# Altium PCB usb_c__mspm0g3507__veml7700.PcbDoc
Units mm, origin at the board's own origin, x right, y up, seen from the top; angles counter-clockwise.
Board outline 68 x 40 mm, 2 copper layers (Top, Bottom), stack 0 mm thick; 33 components, 29 nets, 178 pads, 51 vias.
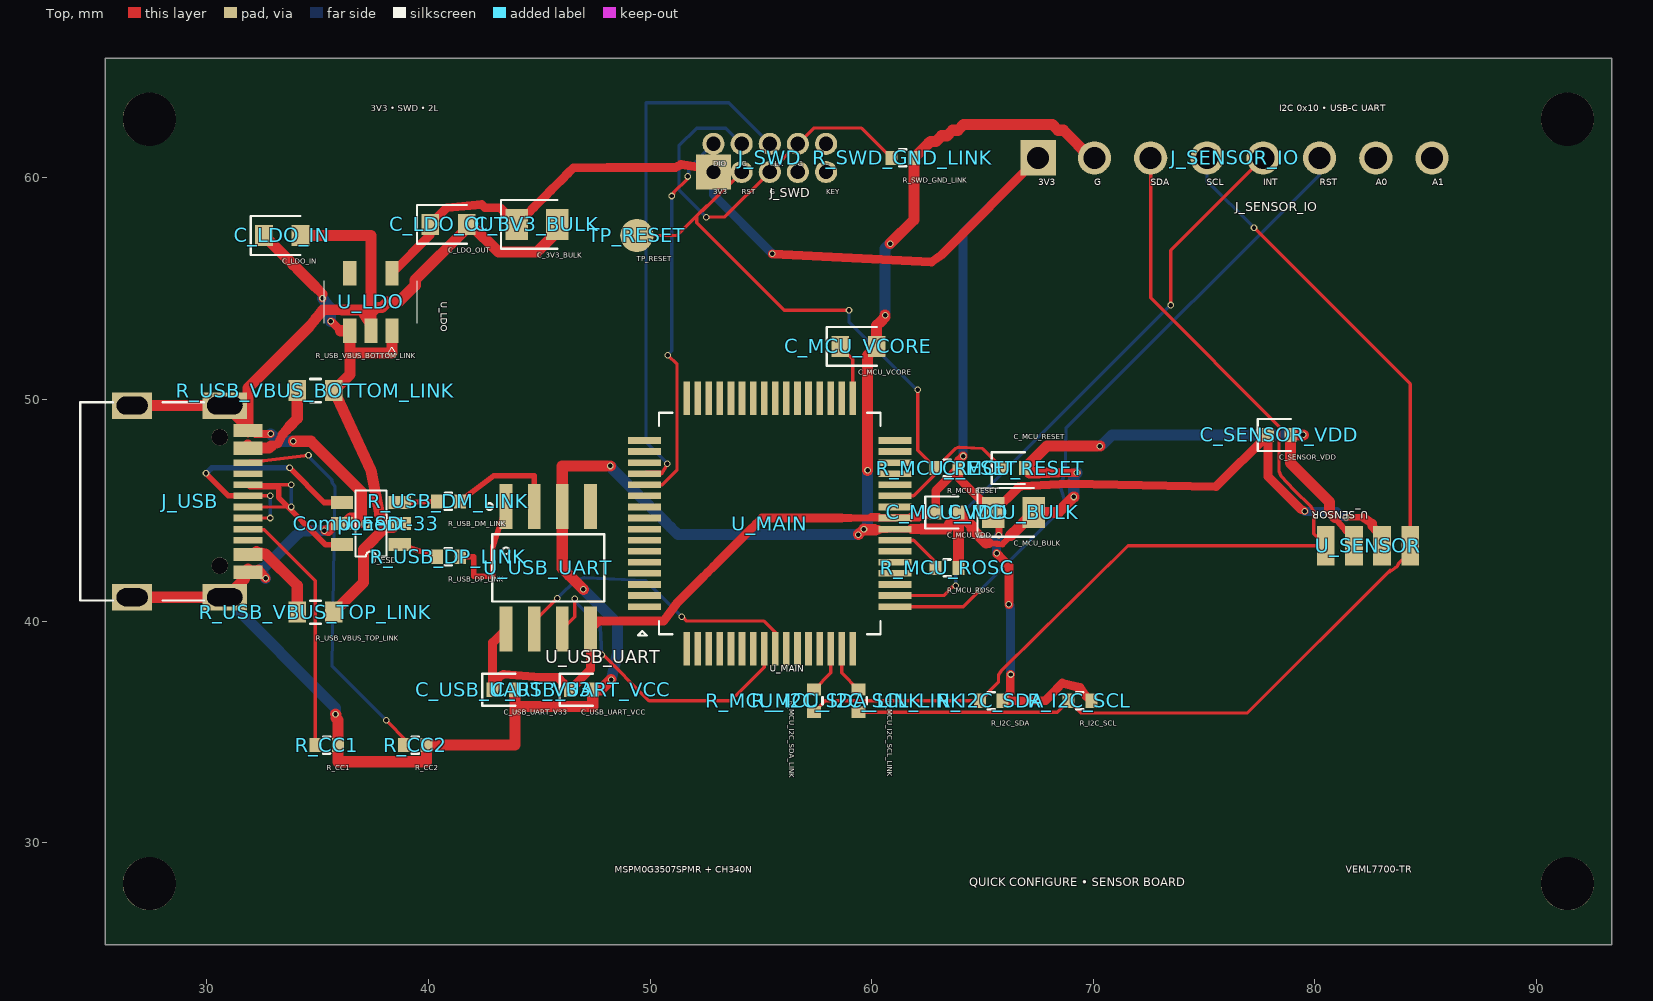
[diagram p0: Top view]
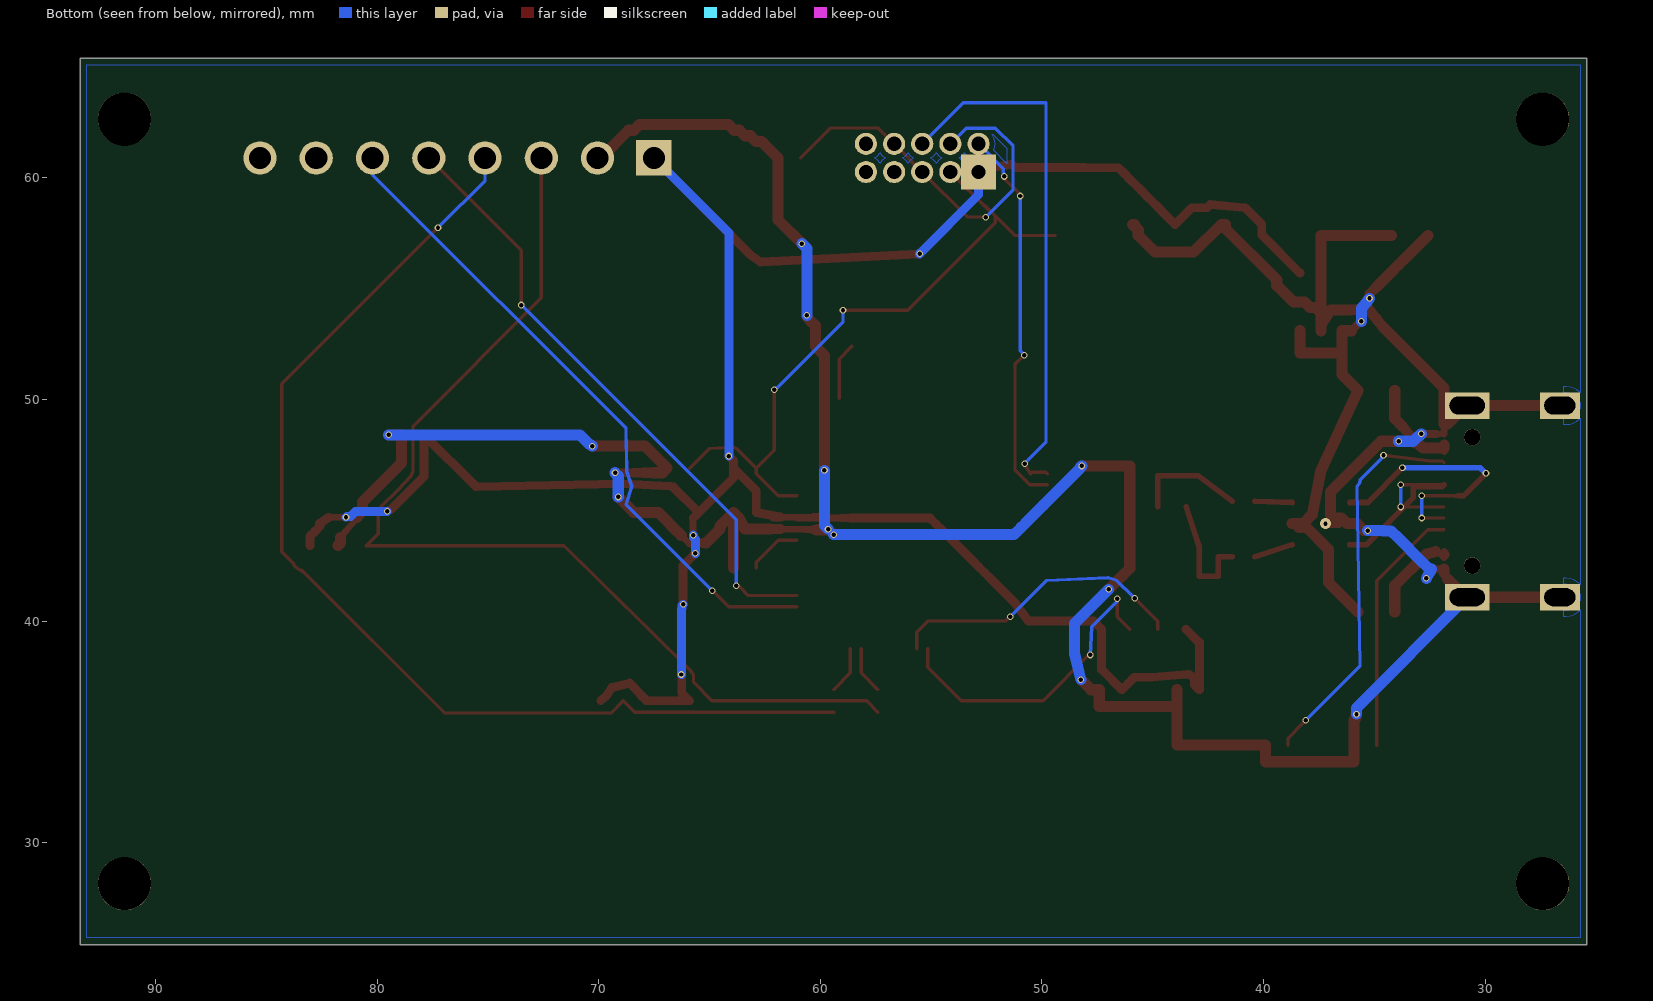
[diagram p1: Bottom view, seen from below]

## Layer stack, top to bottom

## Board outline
25.4,65.4 93.4,65.4 93.4,25.4 25.4,25.4

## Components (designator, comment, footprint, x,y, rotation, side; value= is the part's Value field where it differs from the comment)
C_3V3_BULK "" TSCIRCUIT-2.8500x1.4000mm 44.9,57.9 r0 top
C_LDO_IN "" TSCIRCUIT-2.4500x0.9500mm 33.4,57.4 r0 top
C_LDO_OUT "" TSCIRCUIT-2.4500x0.9500mm 40.9,57.9 r0 top
C_MCU_BULK "" TSCIRCUIT-2.8500x1.4000mm 66.4,44.9 r0 top
C_MCU_RESET "" TSCIRCUIT-1.5600x0.6400mm 66.4,46.9 r0 top
C_MCU_VCORE "" TSCIRCUIT-2.4500x0.9500mm 59.4,52.4 r0 top
C_MCU_VDD "" TSCIRCUIT-1.5600x0.6400mm 63.4,44.9 r0 top
C_SENSOR_VDD "" TSCIRCUIT-1.5600x0.6400mm 78.4,48.4 r0 top
C_USB_UART_V33 "" TSCIRCUIT-1.5600x0.6400mm 43.4,36.9 r0 top
C_USB_UART_VCC "" TSCIRCUIT-1.5600x0.6400mm 46.9,36.9 r0 top
Component-33 "" TSCIRCUIT-0.5000x0.5000mm 37.2,44.4 r0 top
J_SENSOR_IO "" TSCIRCUIT-19.2800x1.5000mm 76.4,60.9 r0 top
J_SWD "" TSCIRCUIT-6.0800x2.2700mm 55.4,60.9 r0 top
J_USB "" TSCIRCUIT-6.7732x9.8502mm 29.112,45.4 r90 top
R_CC1 "" TSCIRCUIT-1.5600x0.6400mm 35.4,34.4 r0 top
R_CC2 "" TSCIRCUIT-1.5600x0.6400mm 39.4,34.4 r0 top
R_I2C_SCL "" TSCIRCUIT-1.5600x0.6400mm 69.4,36.4 r0 top
R_I2C_SDA "" TSCIRCUIT-1.5600x0.6400mm 65.4,36.4 r0 top
R_MCU_I2C_SCL_LINK "" TSCIRCUIT-0.6400x1.5600mm 59.4,36.4 r270 top
R_MCU_I2C_SDA_LINK "" TSCIRCUIT-0.6400x1.5600mm 57.4,36.4 r270 top
R_MCU_RESET "" TSCIRCUIT-1.5600x0.6400mm 63.4,46.9 r0 top
R_MCU_ROSC "" TSCIRCUIT-1.5600x0.6400mm 63.4,42.4 r0 top
R_SWD_GND_LINK "" TSCIRCUIT-1.5600x0.6400mm 61.4,60.9 r0 top
R_USB_DM_LINK "" TSCIRCUIT-1.5600x0.6400mm 40.9,45.4 r0 top
R_USB_DP_LINK "" TSCIRCUIT-1.5600x0.6400mm 40.9,42.9 r0 top
R_USB_VBUS_BOTTOM_LINK "" TSCIRCUIT-2.4500x0.9500mm 34.9,50.4 r0 top
R_USB_VBUS_TOP_LINK "" TSCIRCUIT-2.4500x0.9500mm 34.9,40.4 r0 top
TP_RESET "" TSCIRCUIT-1.5000x1.5000mm 49.4,57.4 r0 top
U_ESD "" TSCIRCUIT-3.6000x2.5000mm 37.4,44.4 r0 top
U_LDO "" TSCIRCUIT-2.5000x3.7000mm 37.4,54.4 r270 top
U_MAIN "" TSCIRCUIT-12.8000x12.8000mm 55.4,44.4 r0 top
U_SENSOR "" TSCIRCUIT-4.6100x1.8000mm 82.4,43.4 r0 top
U_USB_UART "" TSCIRCUIT-4.3840x7.5712mm 45.4,42.4 r0 top

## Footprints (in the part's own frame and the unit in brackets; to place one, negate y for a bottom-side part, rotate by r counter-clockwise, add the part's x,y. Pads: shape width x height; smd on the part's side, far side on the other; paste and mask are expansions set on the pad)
TSCIRCUIT-0.5000x0.5000mm [mm]
TSCIRCUIT-0.6400x1.5600mm [mm]
  rect 0.54x0.64 smd: 1(-0.51,0) 2(0.51,0)
  silkscreen extent -0.15,-0.38 0.15,0.38
TSCIRCUIT-1.5000x1.5000mm [mm]
  round 1.5 smd: 1(0,0)
TSCIRCUIT-1.5600x0.6400mm [mm]
  rect 0.54x0.64 smd: 1(-0.51,0) 2(0.51,0)
  silkscreen extent -0.98,-0.72 0.51,0.72
TSCIRCUIT-2.4500x0.9500mm [mm]
  rect 0.8x0.95 smd: 1(-0.825,0) 2(0.825,0)
  silkscreen extent -1.42,-0.87 0.82,0.87
TSCIRCUIT-2.5000x3.7000mm [mm]
  rect 1.1x0.6 smd: 1(1.3,0.95) 2(1.3,0) 3(1.3,-0.95) 4(-1.3,-0.95) 5(-1.3,0.95)
  silkscreen extent -0.95,-2.1 2.35,2.1
TSCIRCUIT-2.8500x1.4000mm [mm]
  rect 1.025x1.4 smd: 1(-0.913,0) 2(0.913,0)
  silkscreen extent -1.62,-1.1 0.91,1.1
TSCIRCUIT-3.6000x2.5000mm [mm]
  rect 1x0.6 smd: 1(-1.3,-0.95) 2(-1.3,0) 3(-1.3,0.95) 4(1.3,0.95) 5(1.3,0) 6(1.3,-0.95)
  silkscreen extent -0.7,-1.49 0.7,1.49
TSCIRCUIT-4.3840x7.5712mm [mm]
  rect 0.574x2.036 smd: 1(-1.905,2.768) 2(-0.635,2.768) 3(0.635,2.768) 4(1.905,2.768) 5(1.905,-2.768) 6(0.635,-2.768) 7(-0.635,-2.768) 8(-1.905,-2.768)
  silkscreen extent -2.79,-1.52 2.53,2.92
TSCIRCUIT-4.6100x1.8000mm [mm]
  rect 0.8x1.8 smd: 1(1.905,0) 2(0.635,0) 3(-0.635,0) 4(-1.905,0)
TSCIRCUIT-6.0800x2.2700mm [mm]
  rect 1.6x1.6 hole 0.65: 1(-2.54,-0.635)
  round 1 hole 0.65: 2(-2.54,0.635) 3(-1.27,0.635) 4(0,0.635) 5(1.27,0.635) 6(2.54,0.635) 7(2.54,-0.635) 8(1.27,-0.635) 9(0,-0.635) 10(-1.27,-0.635)
TSCIRCUIT-6.7732x9.8502mm [mm]
  rect 0.3x1.3 smd: 1(-3.35,-2.737) 2(-3.05,-2.737) 3(-2.55,-2.737) 4(-2.25,-2.737) 5(-1.75,-2.737) 6(-1.25,-2.737) 7(-0.75,-2.737) 8(-0.25,-2.737) 9(0.25,-2.737) 10(0.75,-2.737) 11(1.25,-2.737) 12(1.75,-2.737) 13(2.55,-2.737) 14(2.25,-2.737) 15(3.35,-2.737) 16(3.05,-2.737)
  rect 1.2x2 hole 0.8 slot 1.6 at 90 deg: 17(-4.325,-1.693) 18(4.325,-1.693)
  rect 1.2x1.8 hole 0.8 slot 1.4 at 90 deg: 19(4.325,2.487) 20(-4.325,2.487)
  round 0.75 hole 0.75 unplated: NPTH-1(-2.9,-1.468) NPTH-2(2.9,-1.468)
  silkscreen extent -4.47,-0.75 4.47,4.83
TSCIRCUIT-12.8000x12.8000mm [mm]
  rect 1.5x0.3 smd: 1(-5.65,-3.75) 2(-5.65,-3.25) 3(-5.65,-2.75) 4(-5.65,-2.25) 5(-5.65,-1.75) 6(-5.65,-1.25) 7(-5.65,-0.75) 8(-5.65,-0.25) 9(-5.65,0.25) 10(-5.65,0.75) 11(-5.65,1.25) 12(-5.65,1.75) 13(-5.65,2.25) 14(-5.65,2.75) 15(-5.65,3.25) 16(-5.65,3.75) 33(5.65,3.75) 34(5.65,3.25) 35(5.65,2.75) 36(5.65,2.25) 37(5.65,1.75) 38(5.65,1.25) 39(5.65,0.75) 40(5.65,0.25) 41(5.65,-0.25) 42(5.65,-0.75) 43(5.65,-1.25) 44(5.65,-1.75) 45(5.65,-2.25) 46(5.65,-2.75) 47(5.65,-3.25) 48(5.65,-3.75)
  rect 0.3x1.5 smd: 17(-3.75,5.65) 18(-3.25,5.65) 19(-2.75,5.65) 20(-2.25,5.65) 21(-1.75,5.65) 22(-1.25,5.65) 23(-0.75,5.65) 24(-0.25,5.65) 25(0.25,5.65) 26(0.75,5.65) 27(1.25,5.65) 28(1.75,5.65) 29(2.25,5.65) 30(2.75,5.65) 31(3.25,5.65) 32(3.75,5.65) 49(3.75,-5.65) 50(3.25,-5.65) 51(2.75,-5.65) 52(2.25,-5.65) 53(1.75,-5.65) 54(1.25,-5.65) 55(0.75,-5.65) 56(0.25,-5.65) 57(-0.25,-5.65) 58(-0.75,-5.65) 59(-1.25,-5.65) 60(-1.75,-5.65) 61(-2.25,-5.65) 62(-2.75,-5.65) 63(-3.25,-5.65) 64(-3.75,-5.65)
  silkscreen extent -5.95,-5.05 5,5
TSCIRCUIT-19.2800x1.5000mm [mm]
  rect 1.6x1.6 hole 1: 1(-8.89,0)
  round 1.5 hole 1: 2(-6.35,0) 3(-3.81,0) 4(-1.27,0) 5(1.27,0) 6(3.81,0) 7(6.35,0) 8(8.89,0)

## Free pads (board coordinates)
  round 2.4 hole 2.4 unplated: NPTH-3(27.4,28.15) NPTH-4(91.4,28.15) NPTH-5(27.4,62.65) NPTH-6(91.4,62.65)

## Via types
v1: diameter 0.3, hole 0.2, Top to Bottom, 50 vias
v2: diameter 0.5, hole 0.2, Top to Bottom, 1 vias

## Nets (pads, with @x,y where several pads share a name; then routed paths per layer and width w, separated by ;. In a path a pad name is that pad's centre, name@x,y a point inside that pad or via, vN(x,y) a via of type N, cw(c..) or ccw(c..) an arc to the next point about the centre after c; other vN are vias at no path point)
".J_SWD > .pin2 to .U_MAIN > .pin12": J_SWD.2 U_MAIN.12 | length 17.5
  Top w0.15: U_MAIN.12 50.542,46.15 51.217,46.825 51.217,51.583 v1(50.8,52) ; v1(50.979,59.182) 51.071,59.274 51.071,59.344 51.697,59.97 v1(51.697,60.066)
  Bottom w0.15: v1(50.8,52) 50.8,52.009 50.979,52.188 v1(50.979,59.182) ; v1(51.697,60.066) 51.741,60.128 51.741,60.248 51.741,60.416 J_SWD.2
".J_SWD > .pin4 to .U_MAIN > .pin13": J_SWD.4 U_MAIN.13 | length 24.4
  Top w0.15: U_MAIN.13 49.819,46.719 50.52,46.719 50.509,46.646 50.708,46.977 v1(50.776,47.106)
  Bottom w0.15: v1(50.776,47.106) 50.749,47.133 49.816,48.066 49.816,63.384 53.551,63.384 J_SWD.4
".U_MAIN > .pin42 to .R_MCU_ROSC > .pin1": R_MCU_ROSC.1 U_MAIN.42 | length 2.5
  Top w0.15: U_MAIN.42 61.889,43.65 62.89,42.649 R_MCU_ROSC.1
GND: C_3V3_BULK.2 C_LDO_IN.2 C_LDO_OUT.2 C_MCU_BULK.2 C_MCU_RESET.2 C_MCU_VCORE.2 C_MCU_VDD.2 C_SENSOR_VDD.2 C_USB_UART_V33.2 C_USB_UART_VCC.2 J_SENSOR_IO.2 J_USB.1 J_USB.2 J_USB.15 J_USB.16 J_USB.17 J_USB.18 J_USB.19 J_USB.20 R_CC1.2 R_CC2.2 R_MCU_ROSC.2 R_SWD_GND_LINK.2 U_ESD.2 U_LDO.2 U_MAIN.41 U_SENSOR.3 U_USB_UART.3 | length 174.7
  Top w0.275: J_USB.16 31.852,48.447 J_USB.16@32.194,48.447 ; 65.294,43.516 65.386,43.516 65.643,43.489 65.9,43.462 66.087,43.662 ; 80.914,44.648 81.16,44.357 U_SENSOR.3@81.405,44.066
  Top w0.3: J_USB.1@31.699,41.9 J_USB.1 J_USB.1@31.849,42.2 ; J_USB.15@31.699,48.9 J_USB.15 ; J_USB.2 J_USB.2@31.946,42.332 ; J_USB.16@31.849,48.6 J_USB.15 ; J_USB.15@31.849,48.9 J_USB.15 ; J_USB.2@32.037,42.35 32.13,42.35 32.224,42.35 J_USB.2@32.318,42.35 ; 60.113,44.15 60.582,44.15 U_MAIN.41 61.144,44.15 61.238,44.15 61.331,44.15 61.425,44.15 61.519,44.15 61.613,44.15 61.706,44.15 61.8,44.15 ; 66.087,43.662 66.274,43.862 ; U_SENSOR.3@81.405,44.066 U_SENSOR.3@81.65,43.775
  Top w0.301: J_USB.2@31.946,42.332 J_USB.2@32.037,42.35 ; U_MAIN.41@60.3,44.118 60.425,44.118 60.55,44.118 60.675,44.118 U_MAIN.41
  Top w0.325: J_USB.16 J_USB.16@31.849,48.6
  Top w0.35: J_USB.16@32.194,48.447 32.537,48.447 v1(32.879,48.447) ; v1(35.293,44.08) v1@35.329,44.098
  Top w0.375: 68.405,46.692 68.834,46.692 v1(69.263,46.692)
  Top w0.4: 36.6,44.4 37.2,44.4 ; 60.175,44.118 60.3,44.118
  Top w0.425: J_USB.2@32.318,42.35 v1(32.65,41.925) ; v1@35.329,44.098 35.475,44.098
  Top w0.437: 67.976,46.692 68.405,46.692
  Top w0.45: 61.8,44.15 62.253,44.15 ; 65.159,43.516 65.294,43.516 ; 80.669,44.939 80.914,44.648
  Top w0.475: 34.92,53.66 35.228,54.041 35.666,54.041 36.103,54.041 ; v1@59.401,43.907 59.645,44.15 60.113,44.15 ; 67.547,46.692 67.976,46.692
  Top w0.481: 34.613,53.279 34.92,53.66
  Top w0.5: J_USB.20 J_USB.17 ; J_USB.19 J_USB.18 ; J_USB.17 30.874,41.075 31.474,41.675 31.699,41.9 ; J_USB.18 30.874,49.725 31.474,49.125 31.699,48.9 ; J_USB.1@31.849,42.2 J_USB.2 ; 31.849,48.9 31.849,50.516 34.613,53.279 ; v1(33.901,48.113) 34.687,48.113 36.983,45.817 36.983,44.817 36.817,44.65 36.483,44.65 36.233,44.4 U_ESD.2 35.778,44.4 35.475,44.098 ; C_LDO_IN.2 37.4,57.4 U_LDO.2 ; v1(35.8,35.8) 35.83,35.77 35.83,35.617 35.91,35.537 R_CC1.2 35.91,33.65 39.91,33.65 R_CC2.2 43.91,34.4 C_USB_UART_V33.2 43.91,36.15 47.41,36.15 C_USB_UART_VCC.2 47.79,36.9 v1(48.243,37.353) ; 36.103,54.041 36.541,54.041 36.978,54.041 37.189,53.713 37.4,53.384 U_LDO.2 ; C_3V3_BULK.2 45.9,57.9 45.65,57.65 45.65,57.4 44.9,56.65 43.15,56.65 41.9,57.9 C_LDO_OUT.2 41.725,57.725 39.4,55.4 39.4,55.15 38.65,54.4 38.15,54.4 37.9,54.15 37.65,54.15 37.4,53.9 U_LDO.2 ; v1(46.987,41.429) 46.67,41.746 46.352,42.064 46.035,42.381 46.035,42.845 46.035,43.31 46.035,43.774 46.035,44.239 46.035,44.703 U_USB_UART.3 46.035,47 v1(48.2,47) ; v1(59.397,43.902) v1@59.401,43.907 ; v1(59.65,44.15) 59.645,44.118 60.05,44.118 60.175,44.118 ; v1(59.813,46.799) 59.816,46.802 59.816,46.82 59.816,51.991 C_MCU_VCORE.2 60.225,52.866 60.225,53.332 60.416,53.523 60.607,53.714 v1(60.608,53.8) v1(60.608,53.8) ; v1(60.834,57.034) 61.91,58.11 R_SWD_GND_LINK.2 62.241,61.231 62.571,61.561 62.65,61.64 62.65,61.65 62.9,61.65 63.15,61.9 63.4,61.9 63.65,62.15 63.9,62.15 64.15,62.4 68.15,62.4 68.4,62.15 68.65,62.15 69.9,60.9 J_SENSOR_IO.2 ; 62.253,44.15 62.707,44.15 63.4,44.15 63.66,44.65 C_MCU_VDD.2 ; R_MCU_ROSC.2 C_MCU_VDD.2 ; 65.159,43.516 64.525,44.15 64.525,44.285 C_MCU_VDD.2 ; 66.274,43.862 66.62,44.208 66.966,44.554 C_MCU_BULK.2 68.419,44.9 v1(69.118,45.6) ; 67.547,46.692 67.118,46.692 C_MCU_RESET.2 67.906,47.896 v1(70.293,47.896) ; v1(79.479,48.4) 79.41,48.4 C_SENSOR_VDD.2 78.91,47.975 78.91,47.55 78.91,47.125 80.669,45.366 80.669,44.939 ; U_SENSOR.3@81.65,43.775 81.65,43.515 U_SENSOR.3
  Bottom w0.5: J_USB.17 35.8,36.081 v1(35.8,35.8) ; v1(32.65,41.925) 32.411,42.35 32.499,42.35 32.505,42.35 32.52,42.35 32.576,42.406 32.909,42.739 33.243,43.072 33.576,43.405 33.909,43.739 34.242,44.072 34.593,44.075 34.943,44.077 v1(35.293,44.08) ; v1(32.879,48.447) 32.966,48.36 33.005,48.36 33.252,48.113 33.577,48.113 v1(33.901,48.113) ; v1(46.987,41.429) 48.525,39.891 48.525,38.525 v1(48.243,37.353) ; v1(48.2,47) 48.281,46.919 48.281,46.883 48.612,46.552 48.943,46.221 49.275,45.889 49.606,45.558 49.937,45.227 50.268,44.896 50.6,44.564 50.931,44.233 51.262,43.902 51.741,43.902 52.219,43.902 52.698,43.902 53.176,43.902 53.655,43.902 54.133,43.902 54.612,43.902 55.09,43.902 55.569,43.902 56.047,43.902 56.526,43.902 57.004,43.902 57.483,43.902 57.961,43.902 58.44,43.902 58.918,43.902 v1(59.397,43.902) ; v1(59.65,44.15) 59.813,44.313 v1(59.813,46.799) ; v1(60.608,53.8) 60.608,56.808 v1(60.834,57.034) ; v1(69.118,45.6) 69.118,46.547 v1(69.263,46.692) ; v1(70.293,47.896) 70.366,47.969 70.408,47.969 70.839,48.4 v1(79.479,48.4)
MAIN_RESET: C_MCU_RESET.1 J_SWD.10 R_MCU_RESET.1 TP_RESET.1 U_MAIN.38 | length 32.6
  Top w0.15: TP_RESET.1 51.23,57.4 52.588,58.757 52.622,58.757 J_SWD.10 52.393,58.533 52.349,58.529 52.11,58.289 52.11,57.965 56.052,54.023 v1(58.975,54.023) ; U_MAIN.38 61.889,45.65 62.89,46.651 R_MCU_RESET.1 ; v1(62.085,50.446) 62.085,47.705 R_MCU_RESET.1 ; C_MCU_RESET.1 65.004,47.786 63.958,47.85 63.776,47.786 R_MCU_RESET.1
  Bottom w0.15: v1(58.975,54.023) 58.975,53.514 61.972,50.516 62.015,50.516 v1(62.085,50.446)
MCU_I2C_SCL_LOCAL: R_MCU_I2C_SCL_LINK.1 U_MAIN.50 | length 2.2
  Top w0.15: U_MAIN.50 58.65,37.66 R_MCU_I2C_SCL_LINK.1
MCU_I2C_SDA_LOCAL: R_MCU_I2C_SDA_LINK.1 U_MAIN.51 | length 2.2
  Top w0.15: R_MCU_I2C_SDA_LINK.1 58.15,37.66 U_MAIN.51
MSPM0_VCORE: C_MCU_VCORE.1 U_MAIN.32 | length 2.6
  Top w0.15: C_MCU_VCORE.1 59.15,51.825 U_MAIN.32
SENSOR_ADDR0: J_SENSOR_IO.7
SENSOR_ADDR1: J_SENSOR_IO.8
SENSOR_INT: J_SENSOR_IO.5 U_MAIN.47 | length 28
  Top w0.15: U_MAIN.47 63.25,41.15 63.639,41.539 63.739,41.539 v1(63.8,41.6) ; v1(73.493,54.26) 73.493,56.723 J_SENSOR_IO.5
  Bottom w0.15: v1(63.8,41.6) 63.8,44.567 73.369,54.136 v1(73.493,54.26)
SENSOR_RESET: J_SENSOR_IO.6 U_MAIN.48 | length 30.1
  Top w0.15: U_MAIN.48 64.143,40.65 64.784,41.292 64.809,41.292 v1(64.878,41.361)
  Bottom w0.15: v1(64.878,41.361) 68.766,45.249 68.512,46.075 68.738,46.75 68.766,48.707 80.21,60.15 J_SENSOR_IO.6
SENSOR_SCL: J_SENSOR_IO.4 R_I2C_SCL.1 R_MCU_I2C_SCL_LINK.2 U_SENSOR.1 | length 50.1
  Top w0.15: R_MCU_I2C_SCL_LINK.2 68.38,35.89 R_I2C_SCL.1 69.44,35.85 69.572,35.85 76.953,35.85 83.402,42.299 83.386,42.228 83.7,42.46 83.788,42.614 84.305,43.132 U_SENSOR.1 84.305,50.7 v1(77.255,57.75)
  Bottom w0.15: J_SENSOR_IO.4 75.13,59.875 77.233,57.772 v1(77.255,57.75)
SENSOR_SDA: J_SENSOR_IO.3 R_I2C_SDA.1 R_MCU_I2C_SDA_LINK.2 U_SENSOR.4 | length 47.1
  Top w0.15: R_MCU_I2C_SDA_LINK.2 57.91,36.4 R_I2C_SDA.1 65.722,37.232 65.722,37.555 65.865,37.771 71.567,43.4 U_SENSOR.4 79.951,43.944 79.951,44.949 79.819,45.175 79.075,45.899 78.472,46.545 78.379,46.771 78.379,48.798 72.59,54.588 J_SENSOR_IO.3
swd-ground-1-to-2: J_SWD.3 J_SWD.5 J_SWD.9 R_SWD_GND_LINK.1 | length 17.8
  Top w0.15: v1(52.539,58.226) 52.538,58.235 52.589,58.235 53.37,58.235 J_SWD.9 J_SWD.5 57.382,62.247 59.375,62.247 59.543,62.247 R_SWD_GND_LINK.1
  Bottom w0.15: v1(52.539,58.226) 51.3,59.469 51.3,61.447 52.095,62.242 53.423,62.242 J_SWD.3
UART_MSP_RX: U_MAIN.57 U_USB_UART.6 | length 14.5
  Top w0.15: U_USB_UART.6 46.6,40.197 v1(46.6,41) ; v1(47.814,38.47) 47.801,38.59 47.787,38.559 49.947,36.4 53.634,36.4 55.15,37.916 U_MAIN.57
  Bottom w0.15: v1(46.6,41) 46.6,40.893 47.743,39.75 v1(47.814,38.47)
UART_MSP_TX: U_MAIN.56 U_USB_UART.7 | length 13.7
  Top w0.15: U_USB_UART.7 44.765,39.984 v1(45.803,41.022) ; v1(51.43,40.198) 51.443,40.185 51.469,40.185 51.654,40 55.142,40 55.65,39.492 U_MAIN.56
  Bottom w0.15: v1(45.803,41.022) v1@45.904,41.123 ; v1@45.905,41.123 46.611,41.829 47.032,41.96 49.799,41.829 v1(51.43,40.198)
usb-dm-device: R_USB_DM_LINK.1 U_ESD.4 | length 1.7
  Top w0.25: U_ESD.4 R_USB_DM_LINK.1
usb-dm-port-tie: J_USB.7 J_USB.9 U_ESD.3 | length 12.2
  Top w0.15: J_USB.9@31.349,45.65 31.38,45.65 31.474,45.65 31.568,45.65 31.662,45.65 31.755,45.65 J_USB.9 v1(32.85,45.65) ; J_USB.7 v1(32.85,44.65)
  Top w0.175: J_USB.9@31.287,45.65 J_USB.9@31.349,45.65
  Top w0.212: 31.193,45.65 J_USB.9@31.287,45.65
  Top w0.25: v1(29.956,46.662) 30.968,45.65 31.099,45.65 31.193,45.65 ; v1(33.727,46.914) v1@33.741,46.9 ; v1@33.742,46.9 35.292,45.35 U_ESD.3
  Bottom w0.15: v1(32.85,44.65) v1(32.85,45.65)
  Bottom w0.25: v1(29.956,46.662) 30.039,46.745 30.048,46.745 30.217,46.914 v1(33.727,46.914)
usb-dm-uart: R_USB_DM_LINK.2 U_USB_UART.2 | length 5.1
  Top w0.25: R_USB_DM_LINK.2 42.95,46.55 44.765,46.55 U_USB_UART.2
usb-dp-device: R_USB_DP_LINK.1 U_ESD.6 | length 1.8
  Top w0.25: U_ESD.6 R_USB_DP_LINK.1
usb-dp-port-tie: J_USB.8 J_USB.10 U_ESD.1 | length 10.5
  Top w0.15: J_USB.8 v1(33.8,45.15) ; J_USB.10 v1(33.8,46.15)
  Top w0.25: J_USB.10 31.948,46.051 33.183,46.051 33.233,46.001 33.232,45.58 35.358,43.444 U_ESD.1
  Bottom w0.15: v1(33.8,45.15) v1(33.8,46.15)
usb-dp-uart: R_USB_DP_LINK.2 U_USB_UART.1 | length 5.6
  Top w0.25: R_USB_DP_LINK.2 42.05,42.9 42.05,42.03 42.9,42.03 42.9,43.35 U_USB_UART.1
USB_CC1: J_USB.6 R_CC1.1 | length 11.4
  Top w0.15: J_USB.6 31.872,44.127 32.589,44.127 34.89,41.826 R_CC1.1
USB_CC2: J_USB.12 R_CC2.1 | length 17.7
  Top w0.15: J_USB.12 31.931,47.218 32.563,47.23 v1(34.584,47.484) ; v1(38.09,35.52) 38.232,35.378 38.89,34.72 R_CC2.1
  Bottom w0.15: v1(34.584,47.484) 34.659,47.409 34.659,47.346 35.635,46.37 35.648,46.251 35.775,46.075 35.64,37.975 v1(38.09,35.52)
USB_VBUS_BOTTOM_LOCAL: J_USB.13 J_USB.14 R_USB_VBUS_BOTTOM_LINK.1 | length 4.5
  Top w0.3: J_USB.14 J_USB.14@31.849,47.8 ; J_USB.13 J_USB.13@32,47.8
  Top w0.4: 32.9,47.9 33.2,48 33.4,48.4
  Top w0.425: 33.4,48.4 33.563,48.592
  Top w0.45: 33.563,48.592 33.725,48.784
  Top w0.475: J_USB.13@31.849,47.8 J_USB.13
  Top w0.5: 32,47.8 32.3,47.8 32.8,47.8 32.9,47.9 ; 33.725,48.784 34.075,49.133 34.075,49.555 34.075,49.978 R_USB_VBUS_BOTTOM_LINK.1
USB_VBUS_TOP_LOCAL: J_USB.3 J_USB.4 R_USB_VBUS_TOP_LINK.1 | length 4.4
  Top w0.275: J_USB.3 J_USB.4@32.129,43.13
  Top w0.3: J_USB.3 31.849,43 J_USB.4 ; J_USB.4@32.129,43.13 J_USB.4@32.232,43.13
  Top w0.5: J_USB.4@32.232,43.13 32.65,43.025 34.075,41.6 R_USB_VBUS_TOP_LINK.1
VBUS5: C_LDO_IN.1 R_USB_VBUS_BOTTOM_LINK.2 R_USB_VBUS_TOP_LINK.2 U_ESD.5 U_LDO.1 U_LDO.3 | length 25.6
  Top w0.325: v1(35.584,53.531) 35.601,53.514 v1@35.622,53.514
  Top w0.35: v1(35.214,54.561) 35.214,54.761
  Top w0.375: v1@35.622,53.514 35.829,53.307 36.036,53.1
  Top w0.45: 34.884,55.091 35.214,54.761
  Top w0.5: C_LDO_IN.1 32.905,57.07 33.235,56.74 33.565,56.41 33.894,56.08 34.224,55.751 34.554,55.421 34.884,55.091 ; R_USB_VBUS_TOP_LINK.2 37.067,41.742 37.067,43.233 38.067,44.233 38.4,44.233 38.567,44.4 U_ESD.5 38.2,44.4 37.8,44.8 37.4,46.8 R_USB_VBUS_BOTTOM_LINK.2 36.45,51.125 U_LDO.3 ; 36.036,53.1 U_LDO.3 ; U_LDO.1 38.35,52.1 36.45,52.1 U_LDO.3
  Bottom w0.5: v1(35.214,54.561) 35.304,54.471 35.304,54.414 35.584,54.134 35.584,53.832 v1(35.584,53.531)
VCC_3V3: C_3V3_BULK.1 C_LDO_OUT.1 C_MCU_BULK.1 C_MCU_VDD.1 C_SENSOR_VDD.1 C_USB_UART_V33.1 C_USB_UART_VCC.1 J_SENSOR_IO.1 J_SWD.1 R_I2C_SCL.2 R_I2C_SDA.2 R_MCU_RESET.2 U_LDO.5 U_MAIN.40 U_SENSOR.2 U_USB_UART.5 U_USB_UART.8 | length 123.9
  Top w0.3: 59.051,44.651 59.45,44.651 59.85,44.65 ; U_MAIN.40@60.3,44.685 60.34,44.685 60.695,44.685 61.05,44.685 61.405,44.685 U_MAIN.40@61.76,44.685 ; U_MAIN.40@60.65,44.65 U_MAIN.40
  Top w0.301: 60.25,44.65 U_MAIN.40@60.65,44.65
  Top w0.312: 59.85,44.65 60.25,44.65 ; U_MAIN.40@60.695,44.662 U_MAIN.40 ; v1(65.737,43.876) 65.737,44.264 C_MCU_BULK.1@65.737,44.651 ; v1(81.404,44.684) 81.793,44.683 82.182,44.682
  Top w0.332: U_MAIN.40@61.797,44.692 U_MAIN.40@61.8,44.692
  Top w0.337: U_MAIN.40@60.34,44.673 U_MAIN.40@60.695,44.662 ; 79.39,45.021 79.475,45.021 v1(79.545,44.951)
  Top w0.363: 58.651,44.651 59.051,44.651 ; 60.3,44.685 59.985,44.685 U_MAIN.40@60.34,44.673
  Top w0.387: v1(65.639,43.053) v1@65.663,43.029
  Top w0.4: U_LDO.5 40.075,57.425 C_LDO_OUT.1 40.327,58.152 40.578,58.403 40.83,58.655 42.4,58.8 42.546,58.655 42.89,58.655 43.233,58.655 43.484,58.403 43.736,58.152 C_3V3_BULK.1 44.243,58.156 44.499,58.412 44.754,58.667 45.01,58.923 45.265,59.179 45.521,59.435 45.776,59.69 46.032,59.946 46.287,60.202 46.543,60.458 46.926,60.458 47.309,60.459 47.692,60.46 48.075,60.461 48.458,60.462 48.841,60.462 49.224,60.463 49.606,60.464 49.989,60.465 50.372,60.465 50.755,60.466 51.138,60.467 51.4,60.6 52.287,60.469 52.67,60.47 J_SWD.1 ; U_USB_UART.8 42.89,39.027 C_USB_UART_V33.1 43.123,37.133 43.123,37.462 43.4,37.6 45.055,37.462 45.442,37.462 45.828,37.462 46.109,37.181 C_USB_UART_VCC.1 47.305,37.815 U_USB_UART.5 47.489,39.816 47.673,40 48.063,40 48.453,40 48.842,40 49.232,40 49.622,40 50.012,40 50.402,40 50.6,40 51.222,40.821 51.496,41.095 51.769,41.368 52.043,41.642 52.316,41.916 52.59,42.189 52.863,42.463 53.137,42.737 53.411,43.01 53.684,43.284 53.958,43.557 54.231,43.831 54.505,44.105 54.778,44.378 55.052,44.652 55.452,44.652 55.851,44.652 56.251,44.652 56.651,44.652 57.051,44.651 57.451,44.651 57.851,44.651 58.251,44.651 58.651,44.651 ; v1(55.519,56.569) 62.7,56.2 63.193,56.552 J_SENSOR_IO.1 ; U_MAIN.40@61.76,44.685 62.115,44.685 61.8,44.692 ; U_MAIN.40@61.797,44.692 C_MCU_VDD.1 62.89,45.88 R_MCU_RESET.2 ; v1(64.128,47.446) 64.031,47.35 63.91,47.229 R_MCU_RESET.2 ; v1@65.663,43.029 65.928,42.764 66.192,42.5 66.192,42.15 66.192,41.8 66.192,41.45 66.192,41.1 v1(66.192,40.75) ; C_MCU_BULK.1@65.737,44.651 C_MCU_BULK.1 ; v1(66.269,37.587) 66.253,37.571 66.253,37.508 66.253,37.125 66.253,36.743 66.081,36.571 R_I2C_SDA.2 66.296,36.4 66.682,36.4 67.068,36.4 67.454,36.4 67.84,36.4 68.041,36.602 68.6,37.2 69.4,37 69.673,36.607 R_I2C_SCL.2 ; 79.39,45.021 79.14,45.271 78.89,45.521 78.64,45.771 78.39,46.021 78.14,46.271 77.89,46.521 77.89,46.897 77.89,47.273 77.89,47.648 77.89,48.024 C_SENSOR_VDD.1 75.533,46.058 68.896,46.194 66.764,46.084 66.631,46.043 C_MCU_BULK.1 ; 82.182,44.682 82.6,44.4 82.569,44.295 82.802,44.062 83.035,43.829 83.035,43.614 U_SENSOR.2 ; R_MCU_RESET.2 63.91,46.478 C_MCU_BULK.1
  Bottom w0.4: J_SWD.1 52.86,59.243 55.496,56.607 55.496,56.606 v1(55.519,56.569) ; v1(64.128,47.446) 64.128,47.833 64.128,48.221 64.128,48.608 64.128,48.996 64.128,49.383 64.128,49.77 64.128,50.158 64.128,50.545 64.128,50.933 64.128,51.32 64.128,51.707 64.128,52.095 64.128,52.482 64.128,52.869 64.128,53.257 64.128,53.644 64.128,54.032 64.128,54.419 64.128,54.806 64.128,55.194 64.128,55.581 64.128,55.968 64.128,56.356 64.128,56.743 64.128,57.131 64.128,57.518 64.41,57.8 64.692,58.082 64.973,58.364 65.255,58.645 65.537,58.927 65.819,59.209 66.101,59.491 66.383,59.773 66.664,60.055 66.946,60.336 67.228,60.618 J_SENSOR_IO.1 ; v1(65.639,43.053) 65.639,43.371 65.639,43.689 65.718,43.768 65.718,43.857 v1(65.737,43.876) ; v1(66.192,40.75) 66.248,40.694 66.248,40.577 66.269,40.557 66.269,40.186 66.269,39.814 66.269,39.443 66.269,39.072 66.269,38.701 66.269,38.329 66.269,37.958 v1(66.269,37.587) ; v1(79.545,44.951) 79.902,44.951 80.259,44.951 80.616,44.951 80.972,44.951 81.2,44.724 81.36,44.724 v1(81.404,44.684)
pads on no net: J_SWD.6 J_SWD.7 J_SWD.8 J_USB.5 J_USB.11 J_USB.NPTH-1 J_USB.NPTH-2 U_LDO.4 U_MAIN.1 U_MAIN.2 U_MAIN.3 U_MAIN.4 U_MAIN.5 U_MAIN.6 U_MAIN.7 U_MAIN.8 U_MAIN.9 U_MAIN.10 U_MAIN.11 U_MAIN.14 U_MAIN.15 U_MAIN.16 U_MAIN.17 U_MAIN.18 U_MAIN.19 U_MAIN.20 U_MAIN.21 U_MAIN.22 U_MAIN.23 U_MAIN.24 U_MAIN.25 U_MAIN.26 U_MAIN.27 U_MAIN.28 U_MAIN.29 U_MAIN.30 U_MAIN.31 U_MAIN.33 U_MAIN.34 U_MAIN.35 U_MAIN.36 U_MAIN.37 U_MAIN.39 U_MAIN.43 U_MAIN.44 U_MAIN.45 U_MAIN.46 U_MAIN.49 U_MAIN.52 U_MAIN.53 U_MAIN.54 U_MAIN.55 U_MAIN.58 U_MAIN.59 U_MAIN.60 U_MAIN.61 U_MAIN.62 U_MAIN.63 U_MAIN.64 U_USB_UART.4
copper on no net:
  other v2: 37.2,44.4

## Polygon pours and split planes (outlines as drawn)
GND on Bottom (solid): 93.1,65.1 25.7,65.1 25.7,50.296 25.725,50.326 25.854,50.432 26.001,50.51 26.16,50.559 26.326,50.575 26.476,50.575 26.476,50.325 26.326,50.325 26.209,50.314 26.096,50.279 25.993,50.224 25.902,50.149 25.827,50.058 25.772,49.955 25.747,49.875 25.7,49.875 25.7,49.575 25.747,49.575 25.772,49.496 25.827,49.392 25.902,49.301 25.993,49.226 26.096,49.171 26.209,49.137 26.326,49.125 26.476,49.125 26.476,48.875 26.326,48.875 26.16,48.891 26.001,48.94 25.854,49.018 25.725,49.124 25.7,49.154 25.7,41.646 25.725,41.676 25.854,41.782 26.001,41.86 26.16,41.909 26.326,41.925 26.476,41.925 26.476,41.675 26.326,41.675 26.209,41.663 26.096,41.629 25.993,41.574 25.902,41.499 25.827,41.408 25.772,41.304 25.747,41.225 25.7,41.225 25.7,40.925 25.747,40.925 25.772,40.845 25.827,40.742 25.902,40.651 25.993,40.576 26.096,40.521 26.209,40.486 26.326,40.475 26.476,40.475 26.476,40.225 26.326,40.225 26.16,40.241 26.001,40.29 25.854,40.368 25.725,40.474 25.7,40.504 25.7,25.7 93.1,25.7
GND on Bottom (solid): 53.495,61.14 53.484,61.118 53.399,61.015 53.591,61.015 53.506,61.118
GND on Bottom (solid): 53.61,60.996 53.61,60.804 53.713,60.889 53.735,60.9 53.713,60.911
GND on Bottom (solid): 57.305,61.14 57.294,61.118 57.2,61.005 57.087,60.911 57.065,60.9 57.087,60.889 57.2,60.795 57.294,60.682 57.305,60.66 57.316,60.682 57.41,60.795 57.523,60.889 57.545,60.9 57.523,60.911 57.41,61.005 57.316,61.118
GND on Bottom (solid): 56.035,61.14 56.024,61.118 55.93,61.005 55.817,60.911 55.795,60.9 55.817,60.889 55.93,60.795 56.024,60.682 56.035,60.66 56.046,60.682 56.14,60.795 56.253,60.889 56.275,60.9 56.253,60.911 56.14,61.005 56.046,61.118
GND on Bottom (solid): 54.765,61.14 54.754,61.118 54.66,61.005 54.547,60.911 54.525,60.9 54.547,60.889 54.66,60.795 54.754,60.682 54.765,60.66 54.776,60.682 54.87,60.795 54.983,60.889 55.005,60.9 54.983,60.911 54.87,61.005 54.776,61.118
GND on Bottom (solid): 52.249,61.967 52.208,61.967 51.575,61.333 51.575,60.639 52.173,61.237 52.167,61.248 52.124,61.389 52.11,61.535 52.124,61.681 52.167,61.822 52.236,61.952
GND on Bottom (solid): 46.203,41.032 46.202,41.031 46.203,41.026

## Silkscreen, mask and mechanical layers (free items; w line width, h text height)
Top Overlay:
  text "3V3 • SWD • 2L" at 37.4,62.9 h0.48
  text "I2C 0x10 • USB-C UART" at 78.4,62.9 h0.5
  text "MSPM0G3507SPMR + CH340N" at 48.4,28.525 h0.52
  text "VEML7700-TR" at 81.4,28.525 h0.55
  text "QUICK CONFIGURE • SENSOR BOARD" at 64.4,27.9 h0.65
